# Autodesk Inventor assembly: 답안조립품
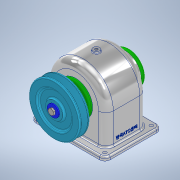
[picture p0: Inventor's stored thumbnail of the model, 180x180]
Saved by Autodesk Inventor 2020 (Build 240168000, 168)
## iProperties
Created: 2022-09
Part Number: 답안조립품
Document SubType Name: Assembly
Designer: com
Author: com
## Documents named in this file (16)
- C:\Users\com\Desktop\720906V1023\답안조립품.iam
- C:\Users\com\Desktop\720906V1023\본체.ipt
- C:\Users\com\Desktop\720906V1023\베어링 6203.ipt
- C:\Users\com\Desktop\720906V1023\뒤커버.ipt
- C:\Users\com\Desktop\720906V1023\앞커버.ipt
- C:\Users\com\Desktop\720906V1023\축.ipt
- C:\Users\com\Desktop\720906V1023\칼라.ipt
- C:\Users\com\Desktop\720906V1023\스퍼기어.ipt
- C:\Users\com\Desktop\720906V1023\키 6 x 6 x 22.ipt
- C:\Users\com\Desktop\720906V1023\볼트 M3 x 10.ipt
- C:\Users\com\Desktop\720906V1023\오일 실 17 x 30 x 8.ipt
- C:\Users\com\Desktop\720906V1023\키 5 x 5 x 18.ipt
- C:\Users\com\Desktop\720906V1023\V-벨트풀리.ipt
- C:\Users\com\Desktop\720906V1023\멈춤나사 M4 x 10.ipt
- C:\Users\com\Desktop\720906V1023\와셔 6 x 22.ipt
- C:\Users\com\Desktop\720906V1023\육각머리볼트 M3 x 8.ipt
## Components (9 placed, 2 different names)
1. ISO 4762 M3 x 10:1
2. ISO 4762 M3 x 10:2
3. ISO 4762 M3 x 10:3
4. ISO 4762 M3 x 10:4
5. V-벨트풀리:1 — 각도:2, 플러쉬:2
6. ISO 4762 M3 x 10:6
7. ISO 4762 M3 x 10:7
8. ISO 4762 M3 x 10:8
9. ISO 4762 M3 x 10:9
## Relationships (2: Angle 1, Flush 1)
- 각도:2 [Angle]: V-벨트풀리:1
- 플러쉬:2 [Flush]: V-벨트풀리:1
